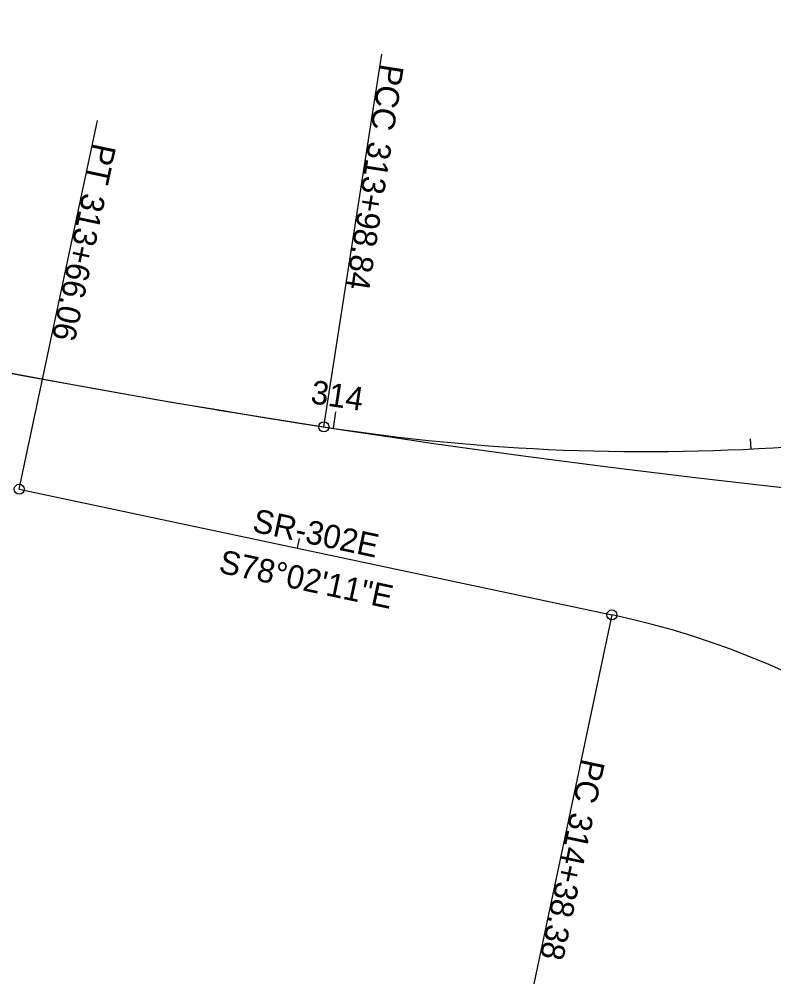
# Model space of a CAD drawing. Extents: x 2047151 to 2048731, y 456453 to 457874.
# Drawn here: x 2047496.9 to 2047586.9, y 456992.3 to 457107.4 of the extents above; entities that cross this region are included whole.
import ezdxf

# ---------------------------------------------------------------- set-up
doc = ezdxf.new("R2010")
doc.units = 0
for name, color, linetype in [('GE_P_Alignment', 7, 'Continuous'), ('GE_P_Alignment_100_Cardinal_Points', 7, 'Continuous'), ('GE_P_Alignment_100_Stations', 7, 'Continuous'), ('GE_P_Alignment_500_Bearings', 7, 'Continuous'), ('GE_P_Alignment_500_Cardinal_Points', 7, 'Continuous'), ('GE_P_Alignment_500_Distances', 7, 'Continuous'), ('GE_P_Alignment_500_Stations', 7, 'Continuous')]:
    doc.layers.add(name, color=color, linetype=linetype)

msp = doc.modelspace()

# ---------------------------------------------------------------- linework, layer by layer
at = {"layer": 'GE_P_Alignment'}
msp.add_line((2047496.87, 457051.35), (2047567.61, 457036.35), dxfattribs=at)
msp.add_line((2047496.87, 457051.35), (2047567.61, 457036.35), dxfattribs=at)
for centre, radius, start, end in [((2047717.44, 458244.57), 1200, 248.79098, 264.8083), ((2047717.44, 458244.57), 1200, 248.79098, 261.16908), ((2047717.44, 458244.57), 1200, 248.79098, 261.16908), ((2047571.6, 457305.84), 250, 261.1691, 287.4713), ((2047571.6, 457305.84), 250, 261.1691, 287.4713), ((2047546.89, 456938.53), 100, 33.2214, 78.0363), ((2047546.89, 456938.53), 100, 33.2214, 78.0363)]:
    msp.add_arc(centre, radius, start, end, dxfattribs=at)
at = {"layer": 'GE_P_Alignment_100_Cardinal_Points'}
msp.add_line((2047533.22, 457058.8), (2047540.13, 457103.27), dxfattribs=at)
msp.add_circle((2047533.22, 457058.8), 0.6, dxfattribs=at)
at = {"layer": 'GE_P_Alignment_100_Stations'}
for p, q in [((2047534.37, 457058.62), (2047534.66, 457060.6)), ((2047584.22, 457056.15), (2047584.16, 457057.35))]:
    msp.add_line(p, q, dxfattribs=at)
at = {"layer": 'GE_P_Alignment_500_Cardinal_Points'}
for p, q in [((2047496.87, 457051.35), (2047506.2, 457095.37)), ((2047567.61, 457036.35), (2047558.29, 456992.33))]:
    msp.add_line(p, q, dxfattribs=at)
for centre in [(2047496.87, 457051.35), (2047567.61, 457036.35)]:
    msp.add_circle(centre, 0.6, dxfattribs=at)
at = {"layer": 'GE_P_Alignment_500_Stations'}
msp.add_line((2047530.07, 457044.31), (2047530.32, 457045.48), dxfattribs=at)

# ---------------------------------------------------------------- texts
at = {"layer": 'GE_P_Alignment_100_Cardinal_Points'}
for s, p in [('PCC', (2047540.01, 457102.22)), ('313+98.84', (2047538.58, 457092.98))]:
    msp.add_text(s, height=2.8, rotation=261.1691, dxfattribs=at).set_placement(p)
at = {"layer": 'GE_P_Alignment_100_Stations'}
msp.add_text('314', height=2.8, rotation=351.4345, dxfattribs=at).set_placement((2047531.54, 457061.63))
at = {"layer": 'GE_P_Alignment_500_Bearings'}
msp.add_text('S78°02\'11"E', height=2.8, rotation=348.0363, dxfattribs=at).set_placement((2047520.56, 457041.42))
at = {"layer": 'GE_P_Alignment_500_Cardinal_Points'}
for s, p in [('PT', (2047505.7, 457092.78)), ('313+66.06', (2047504.44, 457086.82)), ('PC', (2047564.05, 457019.3)), ('314+38.38', (2047562.7, 457012.92))]:
    msp.add_text(s, height=2.8, rotation=258.0363, dxfattribs=at).set_placement(p)
at = {"layer": 'GE_P_Alignment_500_Distances'}
msp.add_text('SR-302E', height=2.8, rotation=348.0363, dxfattribs=at).set_placement((2047524.56, 457046.32))

doc.saveas('drawing.dxf')
